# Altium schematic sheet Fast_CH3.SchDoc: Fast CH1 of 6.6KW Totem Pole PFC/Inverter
size A4
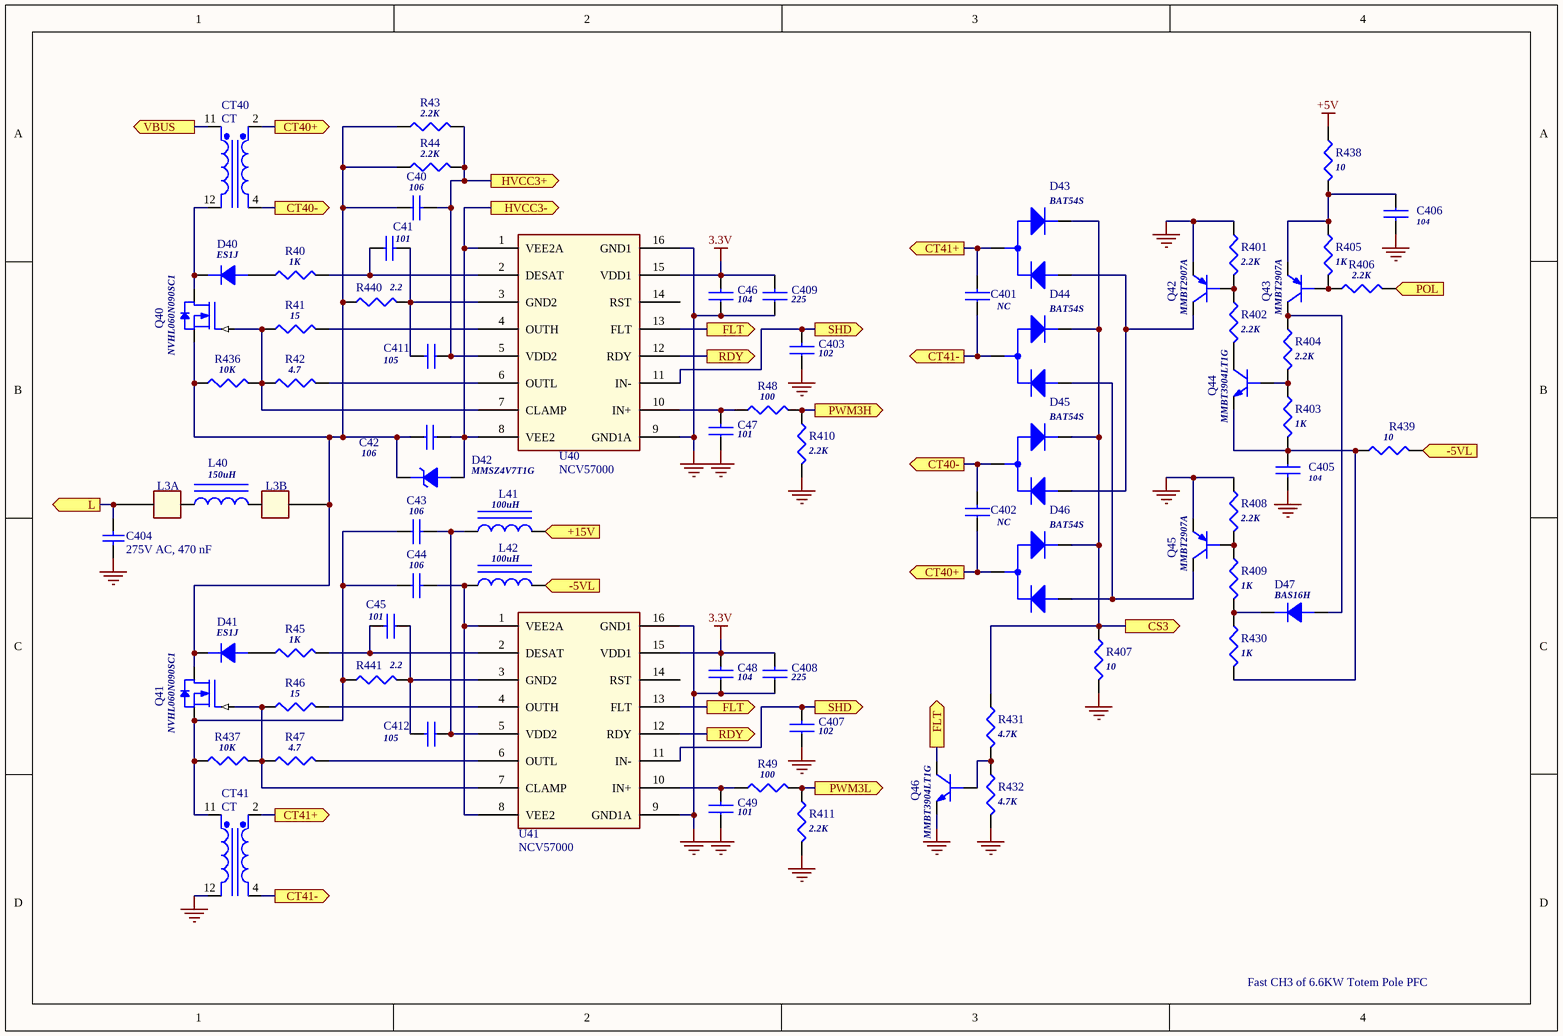
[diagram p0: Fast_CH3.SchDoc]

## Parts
C40  106  [SMT_1206_CM]
C41  101  [SMT_0805_CM]
C42  106  [SMT_1206_CM]
C43  106  [SMT_1206_CM]
C44  106  [SMT_1206_CM]
C45  101  [SMT_0805_CM]
C46  104  [SMT_0805_CM]
C47  101  [SMT_0805_CM]
C48  104  [SMT_0805_CM]
C49  101  [SMT_0805_CM]
C401  NC  [SMT_0805_CM]
C402  NC  [SMT_0805_CM]
C403  102  [SMT_0805_CM]
C404  275V AC, 470 nF  [WCAP-FTX2_18x8x14_CS]
C405  104  [SMT_0805_CM]
C406  104  [SMT_0805_CM]
C407  102  [SMT_0805_CM]
C408  225  [SMT_0805_CM]
C409  225  [SMT_0805_CM]
C411  105  [SMT_0805_CM]
C412  105  [SMT_0805_CM]
CT40  CT  [CT_EE13]
CT41  CT  [CT_EE13]
D40  ES1J  [DO-214AC(SMA)]
D41  ES1J  [DO-214AC(SMA)]
D42  MMSZ4V7T1G  [SOD-123FL]
D43  BAT54S  [SOT-23-3L]
D44  BAT54S  [SOT-23-3L]
D45  BAT54S  [SOT-23-3L]
D46  BAT54S  [SOT-23-3L]
D47  BAS16H  [SOD-323M]
L3A  (no value)  [TermL]
L3B  (no value)  [TermL]
L40  150uH  [INDUCTOR-7*7*3.5]
L41  100uH  [Bead_1210]
L42  100uH  [Bead_1210]
Q40  NVHL060N090SC1  [TO247]
Q41  NVHL060N090SC1  [TO247]
Q42  MMBT2907A  [SOT-23-3L]
Q43  MMBT2907A  [SOT-23-3L]
Q44  MMBT3904LT1G  [SOT-23-3L]
Q45  MMBT2907A  [SOT-23-3L]
Q46  MMBT3904LT1G  [SOT-23-3L]
R40  1K  [SMT_0805_RM]
R41  15  [SMT_1206_RM]
R42  4.7  [SMT_1206_RM]
R43  2.2K  [SMT_1206_RM]
R44  2.2K  [SMT_1206_RM]
R45  1K  [SMT_0805_RM]
R46  15  [SMT_1206_RM]
R47  4.7  [SMT_1206_RM]
R48  100  [SMT_0805_RM]
R49  100  [SMT_0805_RM]
R401  2.2K  [SMT_0805_RM]
R402  2.2K  [SMT_0805_RM]
R403  1K  [SMT_0805_RM]
R404  2.2K  [SMT_0805_RM]
R405  1K  [SMT_0805_RM]
R406  2.2K  [SMT_0805_RM]
R407  10  [SMT_1206_RM]
R408  2.2K  [SMT_0805_RM]
R409  1K  [SMT_0805_RM]
R410  2.2K  [SMT_0805_RM]
R411  2.2K  [SMT_0805_RM]
R430  1K  [SMT_1206_RM]
R431  4.7K  [SMT_0805_RM]
R432  4.7K  [SMT_0805_RM]
R436  10K  [SMT_0805_RM]
R437  10K  [SMT_0805_RM]
R438  10  [SMT_0805_RM]
R439  10  [SMT_0805_RM]
R440  2.2  [SMT_0805_RM]
R441  2.2  [SMT_0805_RM]
U40  NCV57000  [SOP16W]
U41  NCV57000  [SOP16W]

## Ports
+15V (out), -5VL (out), CS3 (out), CT40+ (out), CT40- (out), CT41+ (out), CT41- (out), FLT (out), HVCC3+ (out), HVCC3- (out), L (out), POL (out), PWM3H (out), PWM3L (out), RDY (out), SHD (out), VBUS (out)

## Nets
3.3V: C46.2 C48.2 C408.2 C409.2 U40.15(VDD1) U41.15(VDD1)
+5V: R438.1
PGND: C46.1 C47.1 C48.1 C49.1 C403.1 C404.2 C405.2 C406.2 C407.1 C408.1 C409.1 CT41.12(Pri-) Q42.2(E) Q45.2(E) Q46.2(E) R401.1 R407.2 R408.1 R410.2 R411.2 R432.2 U40.9(GND1A) U40.16(GND1) U41.9(GND1A) U41.16(GND1)
+15V: L41.2 ; port +15V
-5VL: L42.2 R439.2 ; port -5VL
CS3: D43.2 D44.2 D45.2 D46.2 R407.1 R431.1 ; port CS3
CT40+: C402.1 CT40.2(Sec+) D46.3 ; port CT40+
CT40-: C402.2 CT40.4(Sec-) D45.3 ; port CT40-
CT41+: C401.2 CT41.2(Sec+) D43.3 ; port CT41+
CT41-: C401.1 CT41.4(Sec-) D44.3 ; port CT41-
FLT: Q46.3(C) U40.13(FLT) U41.13(FLT) ; port FLT
HVCC3+: C40.2 C411.1 R43.2 R44.2 U40.5(VDD2) ; port HVCC3+
HVCC3-: C42.2 D42.1(ANODE) U40.1(VEE2A) U40.8(VEE2) ; port HVCC3-
L: C404.1 L3A.1 ; port L
POL: R406.2 ; port POL
PWM3H: R48.2 R410.1 ; port PWM3H
PWM3L: R49.2 R411.1 ; port PWM3L
RDY: U40.12(RDY) U41.12(RDY) ; port RDY
SHD: C403.2 C407.2 U40.11(IN-) U41.11(IN-) ; port SHD
VBUS: CT40.11(Pri+) ; port VBUS
NetC40_1: C40.1 C42.1 D41.2(K) D42.2(CATHODE) L3B.1 Q40.3(SOURCE) Q41.2(DRAIN) R43.1 R44.1 R436.1 R440.1
NetC41_1: C41.1 R40.2 U40.2(DESAT)
NetC41_2: C41.2 C411.2 R440.2 U40.3(GND2)
NetC43_1: C43.1 C44.1 CT41.11(Pri+) Q41.3(SOURCE) R437.1 R441.1
NetC43_2: C43.2 C412.1 L41.1 U41.5(VDD2)
NetC44_2: C44.2 L42.1 U41.1(VEE2A) U41.8(VEE2)
NetC45_1: C45.1 C412.2 R441.2 U41.3(GND2)
NetC45_2: C45.2 R45.2 U41.2(DESAT)
NetC47_2: C47.2 R48.1 U40.10(IN+)
NetC49_2: C49.2 R49.1 U41.10(IN+)
NetC405_1: C405.1 Q44.2(E) R403.2 R430.2 R439.1
NetC406_1: C406.1 Q43.2(E) R405.1 R438.2
NetCT40_12: CT40.12(Pri-) D40.2(K) Q40.2(DRAIN)
NetD40_1: D40.1(A) R40.1
NetD41_1: D41.1(A) R45.1
NetD43_1: D43.1 D45.1 Q42.3(C)
NetD44_1: D44.1 D46.1 Q45.3(C)
NetD47_1: D47.1(A) Q43.3(C) R404.1
NetD47_2: D47.2(K) R409.2 R430.1
NetQ40_1: Q40.1(GATE) R41.1 R42.1 R436.2 U40.7(CLAMP)
NetQ41_1: Q41.1(GATE) R46.1 R47.1 R437.2 U41.7(CLAMP)
NetQ42_1: Q42.1(B) R401.2 R402.1
NetQ43_1: Q43.1(B) R405.2 R406.1
NetQ44_1: Q44.1(B) R403.1 R404.2
NetQ44_3: Q44.3(C) R402.2
NetQ45_1: Q45.1(B) R408.2 R409.1
NetQ46_1: Q46.1(B) R431.2 R432.1
NetR41_2: R41.2 U40.4(OUTH)
NetR42_2: R42.2 U40.6(OUTL)
NetR46_2: R46.2 U41.4(OUTH)
NetR47_2: R47.2 U41.6(OUTL)

Not connected (* = marked no-connect by the designer): L40 1 2; U40 14(RST); U41 14(RST)

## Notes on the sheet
- Fast CH3 of 6.6KW Totem Pole PFC

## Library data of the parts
C40-C45 C401 C402 = CAP_1206
C46-C49 C403 C407-C409 C411 C412 = CAP_0805
C404 = 890324025039CS: WCAP-FTX2 Film Capacitors, 18x8x14mm, 275V AC, 470 nF; Rated Voltage: 275V AC; Value: 470 nF
C405 C406 = CAP NP
CT40 CT41 = Trans Cupl: Transformer (Coupled Inductor Model)
D40 D41 = D_SMA(DO-214AC)
D42 = DIODE ZENER
D43-D46 = BAT54S/SOT
D47 = DIODE
L3A L3B = P_1
L40-L42 = INDUCTOR IRON
Q40 Q41 = SICMOS
Q42 Q43 Q45 = Q_PNP_SOT-23-3L
Q44 Q46 = Q_NPN_SOT-23-3L
R40-R49 R406 R436 R437 R439-R441 = R_0805
R401-R405 R407-R411 R430-R432 R438 = R
U40 U41 = U_NCV57000_SO-16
